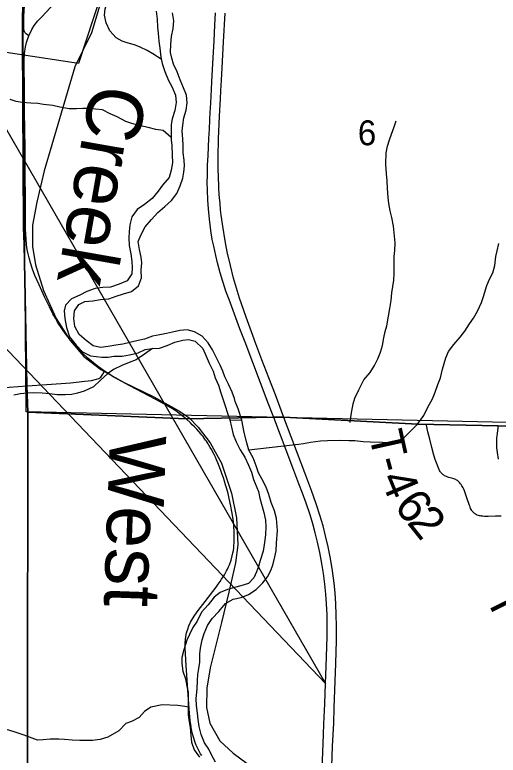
# Model space of a CAD drawing. Extents: x 0 to 34, y 0 to 22.
# Drawn here: x 4.527 to 5.34, y 17.081 to 18.326 of the extents above; entities that cross this region are included whole.
import ezdxf

# ---------------------------------------------------------------- set-up
doc = ezdxf.new("R2010")
doc.units = 0
for name, color, linetype in [('Default', 7, 'Continuous'), ('GM_X_City_Street', 7, 'Continuous'), ('GM_X_Corporation', 7, 'Continuous'), ('GM_X_Interstate_Route', 7, 'Continuous'), ('GM_X_Major_River', 7, 'Continuous'), ('GM_X_Major_River_Text', 7, 'Continuous'), ('GM_X_Minor_River', 7, 'Continuous'), ('GM_X_Rail_Line', 7, 'Continuous'), ('GM_X_Section', 7, 'Continuous'), ('GM_X_Section_Text', 7, 'Continuous'), ('GM_X_State_Route', 7, 'Continuous'), ('GM_X_Township_Road', 7, 'Continuous'), ('GM_X_Township_Road_Text', 7, 'Continuous'), ('SH_Cut_Line', 7, 'Continuous')]:
    doc.layers.add(name, color=color, linetype=linetype)

msp = doc.modelspace()

# ---------------------------------------------------------------- linework, layer by layer
at = {"layer": 'Default'}
msp.add_lwpolyline([(4.5002, 18.1545), (5.0499, 17.2016), (4.3428, 17.9419), (4.5002, 17.9419)], close=True, dxfattribs=at)
at = {"layer": 'GM_X_City_Street'}
msp.add_lwpolyline([(4.5504, 18.2908), (4.5463, 18.294), (4.5441, 18.2964), (4.543, 18.2989), (4.542, 18.303), (4.5425, 18.3233), (4.5438, 18.3504), (4.5442, 18.3738), (4.5433, 18.3874), (4.542, 18.395), (4.5399, 18.404), (4.5388, 18.408), (4.5373, 18.4113), (4.5347, 18.4151), (4.5277, 18.4229), (4.5205, 18.4317), (4.481, 18.4781), (4.4634, 18.5005), (4.4496, 18.52), (4.4317, 18.5443), (4.4197, 18.5562), (4.4037, 18.569)], dxfattribs=at)
at = {"layer": 'GM_X_Corporation'}
msp.add_lwpolyline([(4.4904, 18.7944), (4.5152, 18.7982), (4.5401, 18.7958), (4.5941, 18.7656), (4.6547, 18.7056), (4.6875, 18.6156), (4.7048, 18.5241), (4.704, 18.4796), (4.6852, 18.4001), (4.634, 18.2442), (4.4345, 18.2742), (4.3748, 18.5592), (4.5137, 18.6315)], close=True, dxfattribs=at)
at = {"layer": 'GM_X_Interstate_Route'}
for points in [[(4.9626, 17.6491), (4.9536, 17.673), (4.9145, 17.7755), (4.9056, 17.7983), (4.899, 17.8166), (4.8877, 17.8471), (4.8823, 17.8613), (4.8726, 17.892), (4.8678, 17.9088), (4.865, 17.9214), (4.8617, 17.937), (4.8593, 17.9482), (4.857, 17.9634), (4.8544, 17.9826), (4.8527, 17.9998), (4.8516, 18.0143), (4.851, 18.031), (4.8509, 18.0444), (4.8511, 18.0553), (4.8514, 18.0734), (4.8521, 18.0896), (4.8534, 18.1183), (4.8544, 18.1335), (4.8552, 18.1494), (4.8559, 18.1631), (4.8561, 18.1684), (4.8574, 18.1884), (4.8587, 18.2134), (4.8605, 18.244), (4.8625, 18.282), (4.8637, 18.3084), (4.8646, 18.3293)], [(4.9799, 17.6492), (4.9655, 17.6868), (4.9544, 17.7159), (4.9428, 17.7458), (4.9324, 17.773), (4.9275, 17.7866), (4.9161, 17.8174), (4.9052, 17.8494), (4.8951, 17.8833), (4.8897, 17.9044), (4.8846, 17.9273), (4.881, 17.9459), (4.8771, 17.9709), (4.8745, 17.9892), (4.8734, 17.9979), (4.8723, 18.0096), (4.8715, 18.0175), (4.8705, 18.0329), (4.8702, 18.042), (4.8697, 18.0489), (4.8694, 18.0709), (4.8692, 18.0914), (4.8696, 18.1134), (4.8698, 18.1179), (4.8702, 18.1301), (4.8713, 18.1554), (4.8729, 18.1848), (4.8738, 18.1984), (4.8746, 18.2162), (4.8758, 18.2369), (4.8783, 18.2808), (4.8807, 18.3289)], [(5.0438, 17.0433), (5.0455, 17.0861), (5.0465, 17.1159), (5.0471, 17.1339), (5.0485, 17.1674), (5.0499, 17.2016), (5.0509, 17.2301), (5.0525, 17.2804), (5.0527, 17.2979), (5.0524, 17.3172), (5.0516, 17.3358), (5.0504, 17.3519), (5.0487, 17.3687), (5.0463, 17.3865), (5.0435, 17.4037), (5.0401, 17.4221), (5.0364, 17.4391), (5.0326, 17.4548), (5.0283, 17.4704), (5.0238, 17.4854), (5.0173, 17.5048), (5.0111, 17.5218), (5.0051, 17.5374), (4.9949, 17.5641), (4.9626, 17.6491)], [(5.0604, 17.0619), (5.0617, 17.0961), (5.0638, 17.1352), (5.0646, 17.1606), (5.0658, 17.2059), (5.067, 17.2351), (5.0681, 17.2742), (5.0683, 17.2984), (5.068, 17.317), (5.0673, 17.3356), (5.066, 17.3542), (5.0644, 17.3703), (5.0616, 17.3912), (5.0582, 17.412), (5.0544, 17.4315), (5.05, 17.4502), (5.0456, 17.467), (5.0404, 17.4848), (5.0343, 17.5037), (5.0268, 17.5248), (5.0151, 17.5562), (4.9799, 17.6492)]]:
    msp.add_lwpolyline(points, dxfattribs=at)
at = {"layer": 'GM_X_Major_River'}
msp.add_line((4.8891, 17.6449), (4.909, 17.6445), dxfattribs=at)
for points in [[(4.7648, 18.3323), (4.7665, 18.3187), (4.7674, 18.305), (4.7683, 18.2952), (4.7696, 18.2815), (4.7709, 18.2698), (4.7726, 18.255), (4.775, 18.2444), (4.7797, 18.2308), (4.7855, 18.2157), (4.791, 18.2055), (4.7976, 18.1908), (4.7985, 18.1787), (4.7964, 18.165), (4.792, 18.1513), (4.7902, 18.1418), (4.79, 18.1285), (4.7901, 18.116), (4.791, 18.1062), (4.7919, 18.0902), (4.7921, 18.0773), (4.7903, 18.0648), (4.787, 18.0526), (4.7758, 18.0396), (4.7683, 18.0293), (4.7582, 18.0174), (4.7451, 18.007), (4.733, 17.9989), (4.724, 17.9866), (4.7204, 17.9729), (4.7194, 17.9612), (4.7187, 17.9509), (4.7196, 17.9384), (4.7221, 17.9244), (4.7241, 17.9115), (4.7246, 17.9009), (4.724, 17.8903), (4.7162, 17.8788), (4.7029, 17.8734), (4.6882, 17.8683), (4.6749, 17.8673), (4.662, 17.8657), (4.6484, 17.8606), (4.6363, 17.8548), (4.6224, 17.8485), (4.6122, 17.8378), (4.6101, 17.8283), (4.611, 17.8154), (4.6138, 17.8002), (4.6189, 17.7844), (4.6301, 17.7705), (4.6412, 17.7596), (4.6542, 17.7525), (4.6637, 17.7515), (4.6736, 17.7505), (4.6839, 17.7506), (4.6937, 17.7519), (4.7078, 17.752), (4.7203, 17.7545), (4.7347, 17.7577), (4.7464, 17.7631), (4.7585, 17.7652), (4.7706, 17.7657), (4.7835, 17.77), (4.7963, 17.7758), (4.8096, 17.779), (4.8191, 17.7799), (4.8305, 17.7774), (4.8432, 17.765), (4.849, 17.7522), (4.8541, 17.7401), (4.8607, 17.7269), (4.8642, 17.7156)], [(4.8095, 18.0514), (4.8116, 18.0616), (4.8123, 18.0719), (4.8118, 18.0817), (4.8101, 18.0942), (4.8103, 18.1071), (4.8095, 18.1177), (4.8089, 18.1306), (4.8096, 18.1405), (4.8117, 18.153), (4.8154, 18.1656), (4.8171, 18.1781), (4.8158, 18.1907), (4.8111, 18.2035), (4.8053, 18.2167), (4.8002, 18.2303), (4.7943, 18.2431), (4.7912, 18.2529), (4.7892, 18.2628), (4.7894, 18.2764), (4.7908, 18.2897), (4.7936, 18.303), (4.7946, 18.316), (4.7926, 18.3292)], [(4.8966, 17.6808), (4.893, 17.6913), (4.8868, 17.7048), (4.8805, 17.7173), (4.877, 17.7271), (4.8723, 17.7369), (4.8661, 17.7505), (4.8595, 17.7625), (4.8525, 17.7746), (4.8425, 17.7855), (4.8295, 17.7929), (4.817, 17.7966), (4.8045, 17.7953), (4.7923, 17.7925), (4.7825, 17.7901), (4.7708, 17.7877), (4.7586, 17.7856), (4.7454, 17.7806), (4.7348, 17.7785), (4.709, 17.7722), (4.6969, 17.7705), (4.684, 17.7685), (4.6715, 17.7664), (4.659, 17.7697), (4.6471, 17.7783), (4.6352, 17.7887), (4.6278, 17.8019), (4.6262, 17.8152), (4.6275, 17.8285), (4.635, 17.8388), (4.6448, 17.8439), (4.6585, 17.8451), (4.6713, 17.8476), (4.685, 17.8485), (4.6975, 17.8528), (4.71, 17.8568), (4.7232, 17.8607), (4.7349, 17.8703), (4.7404, 17.8837), (4.7399, 17.8966), (4.7405, 17.9091), (4.7396, 17.9185), (4.7368, 17.9314), (4.7348, 17.9447), (4.7396, 17.9569), (4.7462, 17.9698), (4.7571, 17.9817), (4.7676, 17.9936), (4.7793, 18.0036), (4.7905, 18.014), (4.7995, 18.0255), (4.8051, 18.0384), (4.8095, 18.0514)], [(4.8642, 17.7156), (4.8697, 17.7031), (4.8736, 17.6906), (4.8768, 17.6801), (4.8807, 17.6683), (4.8847, 17.6563), (4.8891, 17.6449)], [(4.909, 17.6445), (4.9028, 17.6633), (4.8976, 17.6761), (4.8966, 17.6808)], [(4.8891, 17.6449), (4.8946, 17.6206), (4.8993, 17.6082), (4.9062, 17.5946), (4.9143, 17.5821), (4.9201, 17.5689), (4.9251, 17.5568), (4.9287, 17.5447), (4.9372, 17.5243), (4.9392, 17.5133), (4.9419, 17.5035), (4.9459, 17.4895), (4.9486, 17.4762), (4.9495, 17.4652), (4.9489, 17.4516), (4.9474, 17.4386), (4.9449, 17.4242), (4.9401, 17.4086), (4.9372, 17.3987), (4.9338, 17.3892), (4.9294, 17.3793), (4.92, 17.3697), (4.9071, 17.3658), (4.8965, 17.3631), (4.8851, 17.3599), (4.8726, 17.3549), (4.8624, 17.3468), (4.8523, 17.3342), (4.8414, 17.3216), (4.8336, 17.3064), (4.8268, 17.2961), (4.8208, 17.2843), (4.8164, 17.2744), (4.8112, 17.2584), (4.8079, 17.2455), (4.808, 17.2352), (4.8096, 17.2227), (4.8143, 17.2095), (4.8167, 17.1974), (4.819, 17.1868), (4.8188, 17.1754), (4.8185, 17.1621), (4.819, 17.1488), (4.8206, 17.1375), (4.8222, 17.128), (4.8231, 17.1151), (4.8243, 17.103), (4.829, 17.0901), (4.8378, 17.0777)], [(4.8645, 17.0692), (4.8579, 17.0817), (4.8533, 17.0915), (4.8464, 17.102), (4.8405, 17.116), (4.8374, 17.1296), (4.8354, 17.1414), (4.8342, 17.1516), (4.8325, 17.1649), (4.8324, 17.1763), (4.8338, 17.193), (4.8344, 17.2066), (4.8351, 17.2169), (4.8365, 17.2271), (4.8383, 17.2378), (4.8386, 17.2514), (4.8396, 17.2609), (4.8422, 17.2754), (4.8459, 17.286), (4.8515, 17.299), (4.8593, 17.3108), (4.8706, 17.323), (4.8815, 17.3364), (4.8947, 17.3433), (4.908, 17.3461), (4.9201, 17.3512), (4.9329, 17.36), (4.9442, 17.3711), (4.9521, 17.381), (4.957, 17.3906), (4.9611, 17.4008), (4.9647, 17.4145), (4.9669, 17.4248), (4.9676, 17.4377), (4.9689, 17.4589), (4.9672, 17.4794), (4.9637, 17.4923), (4.9586, 17.5059), (4.9543, 17.5195), (4.9497, 17.5316), (4.9427, 17.5456), (4.9373, 17.5558), (4.9334, 17.5679), (4.9283, 17.5811), (4.9206, 17.5939), (4.9175, 17.6064), (4.9132, 17.6235), (4.909, 17.6445)]]:
    msp.add_lwpolyline(points, dxfattribs=at)
at = {"layer": 'GM_X_Minor_River'}
for points in [[(4.7733, 18.2517), (4.7592, 18.2606), (4.7496, 18.2662), (4.7382, 18.2718), (4.7287, 18.2755), (4.718, 18.2785), (4.7078, 18.2819), (4.6978, 18.2875), (4.6868, 18.2992), (4.681, 18.3124), (4.6782, 18.3257), (4.6793, 18.3359), (4.6823, 18.3454), (4.6936, 18.3546), (4.7061, 18.3569), (4.7183, 18.3589), (4.7311, 18.3628), (4.7417, 18.3674), (4.7563, 18.3764)], [(4.7901, 18.1197), (4.7767, 18.1313), (4.7642, 18.1332), (4.7512, 18.1365), (4.7387, 18.1394), (4.7239, 18.1431), (4.7136, 18.1469), (4.6991, 18.1547), (4.6877, 18.1596), (4.6747, 18.166), (4.6629, 18.1674), (4.6527, 18.1685), (4.6417, 18.1684), (4.631, 18.1679), (4.6185, 18.1682), (4.6026, 18.1708), (4.5908, 18.1734), (4.5756, 18.1755), (4.5657, 18.177), (4.5539, 18.1777), (4.5395, 18.1787), (4.5296, 18.1802), (4.5193, 18.1835)], [(5.0912, 17.6403), (5.0935, 17.6567), (5.0964, 17.6722), (5.099, 17.6817), (5.1057, 17.6954), (5.1144, 17.7125), (5.1249, 17.7247), (5.132, 17.7366), (5.1377, 17.7476), (5.1425, 17.759), (5.1455, 17.77), (5.1481, 17.7829), (5.1499, 17.7936), (5.1529, 17.8031), (5.1558, 17.8194), (5.158, 17.8323), (5.1602, 17.8456), (5.1612, 17.8585), (5.1649, 17.8798), (5.1652, 17.8908), (5.1655, 17.9025), (5.1654, 17.9196), (5.1665, 17.9298), (5.1668, 17.9427), (5.1655, 17.9594), (5.1643, 17.9704), (5.1612, 17.9852), (5.1588, 17.9962), (5.1564, 18.009), (5.1552, 18.0189), (5.154, 18.0341), (5.1535, 18.047), (5.1523, 18.0587), (5.1515, 18.075), (5.1521, 18.094), (5.1539, 18.105), (5.1573, 18.116), (5.1606, 18.1255), (5.1651, 18.1377), (5.1684, 18.1479)], [(5.2044, 17.6378), (5.2154, 17.6525), (5.2221, 17.6662), (5.23, 17.6803), (5.2345, 17.6917), (5.2386, 17.7043), (5.2431, 17.7157), (5.2468, 17.7301), (5.2523, 17.7491), (5.2568, 17.7597), (5.2658, 17.7716), (5.2764, 17.7838), (5.2843, 17.7941), (5.2922, 17.8063), (5.2986, 17.8158), (5.3057, 17.8276), (5.3125, 17.8424), (5.3158, 17.8523), (5.321, 17.8709), (5.3255, 17.8816), (5.3311, 17.8922), (5.3345, 17.9048), (5.3366, 17.9196), (5.3388, 17.9294), (5.3414, 17.9416)], [(4.7586, 17.7652), (4.745, 17.7553), (4.7314, 17.7461), (4.7197, 17.7414), (4.7072, 17.7364), (4.6932, 17.7299), (4.683, 17.7226), (4.6713, 17.7119), (4.6596, 17.7005), (4.6437, 17.6932), (4.6323, 17.6897), (4.6228, 17.6877), (4.6118, 17.6869), (4.5985, 17.6868), (4.586, 17.689), (4.5731, 17.69), (4.559, 17.6907), (4.548, 17.6899), (4.5366, 17.6887), (4.5256, 17.6863)], [(5.2044, 17.6378), (5.1828, 17.6159), (5.1746, 17.6086), (5.1621, 17.6054), (5.1457, 17.607), (5.1252, 17.6075), (5.1134, 17.608), (5.0989, 17.6097), (5.089, 17.61), (5.073, 17.6101), (5.0529, 17.6098), (5.0411, 17.6092), (5.0244, 17.6071), (5.0127, 17.6046), (5.0043, 17.6037), (4.9941, 17.6024), (4.9206, 17.5939)], [(4.5428, 17.1148), (4.5294, 17.1193), (4.5172, 17.1234), (4.5027, 17.126), (4.4887, 17.1255), (4.4781, 17.1254), (4.4682, 17.1269), (4.4571, 17.1302), (4.4469, 17.1324), (4.4355, 17.1358), (4.426, 17.1391), (4.4123, 17.1428), (4.394, 17.1507), (4.3784, 17.1589), (4.3669, 17.1645), (4.3521, 17.1701), (4.3388, 17.1746), (4.3281, 17.1779), (4.3182, 17.1805), (4.3083, 17.1854), (4.2988, 17.1921), (4.2854, 17.203), (4.2736, 17.2125), (4.2621, 17.2211)], [(4.8185, 17.1621), (4.8134, 17.1631), (4.8016, 17.1648), (4.775, 17.1659), (4.7557, 17.1618), (4.7455, 17.1548), (4.7361, 17.1448), (4.7233, 17.1378), (4.7139, 17.1346), (4.7022, 17.1223), (4.6834, 17.1114), (4.6709, 17.1074), (4.658, 17.1061), (4.6474, 17.1059), (4.6367, 17.1061), (4.6238, 17.1067), (4.6108, 17.1076), (4.6009, 17.1079), (4.5865, 17.108), (4.5747, 17.1071), (4.5652, 17.1066), (4.5428, 17.1148)]]:
    msp.add_lwpolyline(points, dxfattribs=at)
at = {"layer": 'GM_X_Rail_Line'}
msp.add_lwpolyline([(2.1, 18.7171), (2.1, 14.1), (4.5781, 14.1), (4.5658, 14.9668), (4.5509, 15.5331), (4.5478, 16.582), (4.5489, 17.6578), (4.5474, 17.7028), (4.5429, 17.9404), (4.5419, 17.9684), (4.5402, 18.2851), (4.5408, 18.3763), (4.5397, 18.3961), (4.5397, 18.4045), (4.5399, 18.4424), (4.5403, 18.5054), (4.5462, 18.6416), (3.8456, 18.6615), (3.8442, 18.6615), (2.9234, 18.6945), (2.9222, 18.6946), (2.7892, 18.6993), (2.7864, 18.6994)], close=True, dxfattribs=at)
for points in [[(4.5408, 18.3763), (4.5402, 18.2851), (4.5419, 17.9684), (4.5429, 17.9404), (4.5474, 17.7028), (4.5489, 17.6578), (4.8158, 17.6467), (4.9624, 17.6496), (4.9797, 17.6498), (5.2052, 17.638), (5.3403, 17.635), (5.6743, 17.6274), (5.6656, 16.9939), (5.6628, 16.7899), (5.6628, 16.7878), (5.6614, 16.7344), (5.6594, 16.6485), (5.9824, 16.6436), (7.149, 16.6283)], [(4.6826, 18.3838), (4.6563, 18.2957), (4.6283, 18.2384), (4.5765, 18.0637), (4.5642, 18.0108), (4.5567, 17.9726), (4.5567, 17.9364), (4.5619, 17.9054), (4.5752, 17.8626), (4.5966, 17.8153), (4.6202, 17.7784), (4.6431, 17.7518), (4.6718, 17.7296), (4.7102, 17.7082), (4.7611, 17.6839), (4.8039, 17.6595), (4.8164, 17.6514)], [(7.149, 16.6283), (5.9824, 16.6436), (5.6594, 16.6485), (5.6614, 16.7344), (5.6628, 16.7878), (5.6628, 16.7899), (5.6656, 16.9939), (5.6743, 17.6274), (5.3403, 17.635), (5.2052, 17.638), (4.9797, 17.6498), (4.9624, 17.6496), (4.8158, 17.6467), (4.5489, 17.6578), (4.5478, 16.582), (4.5509, 15.5331), (4.5658, 14.9668), (4.5781, 14.1), (8.76, 14.1)], [(4.8164, 17.6514), (4.8198, 17.6491), (4.8353, 17.6329), (4.8558, 17.6063), (4.8748, 17.5719), (4.8919, 17.5215), (4.9003, 17.4805), (4.9022, 17.435), (4.8984, 17.4048), (4.8874, 17.3553), (4.8748, 17.3044), (4.8556, 17.2283), (4.8504, 17.1936), (4.8497, 17.1611), (4.8549, 17.1353), (4.8718, 17.1053), (4.8946, 17.0844), (4.9288, 17.0592)]]:
    msp.add_lwpolyline(points, dxfattribs=at)
at = {"layer": 'GM_X_Section'}
msp.add_lwpolyline([(5.7131, 18.626), (5.685, 17.6333), (4.5464, 17.6585), (4.5407, 18.3336), (4.5473, 18.6426)], close=True, dxfattribs=at)
at = {"layer": 'GM_X_State_Route'}
for points in [[(4.5718, 18.3223), (4.5946, 18.3462)], [(4.5473, 18.2813), (4.5483, 18.2847), (4.5504, 18.2908), (4.5556, 18.3014), (4.5596, 18.3078), (4.5657, 18.316), (4.5718, 18.3223)], [(4.678, 17.7266), (4.6678, 17.7344), (4.6596, 17.7406), (4.6497, 17.7489), (4.6405, 17.7576), (4.6325, 17.7659), (4.6262, 17.7727), (4.6203, 17.7796), (4.6166, 17.7842), (4.6122, 17.7899), (4.6073, 17.7968), (4.5991, 17.8095), (4.5953, 17.816), (4.5913, 17.8231), (4.5854, 17.8348), (4.5773, 17.852), (4.5682, 17.872), (4.561, 17.8875), (4.5567, 17.8983), (4.5532, 17.9091), (4.5511, 17.9173), (4.5493, 17.9243), (4.548, 17.9317), (4.5469, 17.9392), (4.546, 17.949), (4.5455, 17.9571), (4.5453, 17.9662), (4.5452, 17.9747), (4.5448, 17.9855), (4.5448, 18.023), (4.5446, 18.0518), (4.5444, 18.0953), (4.544, 18.1383), (4.5435, 18.1586), (4.5435, 18.1689), (4.5433, 18.1908), (4.5433, 18.2113), (4.5428, 18.2311), (4.543, 18.2504), (4.5435, 18.2607), (4.545, 18.2723), (4.5468, 18.2796), (4.5473, 18.2813)], [(4.5021, 17.6986), (4.5476, 17.7023), (4.5809, 17.7045), (4.6206, 17.7073), (4.6449, 17.7098), (4.6561, 17.7112), (4.6647, 17.7133), (4.6687, 17.7146), (4.6717, 17.717), (4.675, 17.7216), (4.678, 17.7266)], [(4.816, 17.6461), (4.806, 17.6542), (4.7979, 17.6602), (4.783, 17.6693), (4.7631, 17.6799), (4.7207, 17.702), (4.6934, 17.7165), (4.678, 17.7266)], [(4.8415, 17.0806), (4.8395, 17.0837), (4.8372, 17.0878), (4.8355, 17.0914), (4.834, 17.0945), (4.8323, 17.0981), (4.8312, 17.101), (4.8299, 17.1044), (4.8287, 17.1081), (4.8277, 17.1114), (4.8266, 17.1156), (4.8256, 17.1198), (4.8245, 17.1245), (4.8238, 17.1289), (4.8223, 17.1393), (4.8211, 17.1517), (4.8194, 17.1746), (4.8153, 17.232), (4.814, 17.2514), (4.8136, 17.2619), (4.8137, 17.2693), (4.8141, 17.2755), (4.8149, 17.2809), (4.8162, 17.2869), (4.818, 17.2928), (4.8201, 17.2986), (4.8229, 17.3048), (4.8261, 17.3107), (4.8297, 17.3165), (4.8354, 17.3245), (4.8471, 17.3398), (4.8657, 17.3639), (4.869, 17.3685), (4.8723, 17.3731), (4.875, 17.377), (4.8775, 17.3808), (4.8797, 17.3842), (4.8816, 17.3879), (4.8834, 17.391), (4.8851, 17.3942), (4.8867, 17.3981), (4.888, 17.4014), (4.8908, 17.4091), (4.8929, 17.4163), (4.8941, 17.4215), (4.8949, 17.4254), (4.8954, 17.4293), (4.8958, 17.4328), (4.8963, 17.4392), (4.8963, 17.4448), (4.896, 17.4554), (4.8953, 17.4672), (4.8942, 17.4778), (4.8923, 17.491), (4.8907, 17.5), (4.8878, 17.5127), (4.8859, 17.5209), (4.8836, 17.529), (4.8817, 17.536), (4.8797, 17.5421), (4.878, 17.5478), (4.876, 17.5534), (4.8737, 17.5598), (4.8708, 17.5674), (4.8689, 17.5725), (4.8666, 17.5778), (4.8645, 17.5825), (4.8624, 17.5869), (4.8603, 17.5909), (4.8583, 17.5946), (4.8559, 17.5988), (4.8535, 17.6027), (4.8524, 17.6045), (4.8511, 17.6065), (4.8496, 17.6089), (4.848, 17.611), (4.8459, 17.6141), (4.8438, 17.6168), (4.8419, 17.6193), (4.84, 17.6215), (4.8364, 17.6257), (4.8331, 17.6293), (4.8293, 17.6333), (4.8257, 17.6368), (4.8224, 17.64), (4.816, 17.6461)]]:
    msp.add_lwpolyline(points, dxfattribs=at)
at = {"layer": 'GM_X_Township_Road'}
for points in [[(5.3453, 17.483), (5.336, 17.4828), (5.3236, 17.4824), (5.3201, 17.4824), (5.3171, 17.4825), (5.3146, 17.4828), (5.3124, 17.4831), (5.3105, 17.4834), (5.3088, 17.4839), (5.307, 17.4843), (5.3052, 17.485), (5.304, 17.4855), (5.3024, 17.4864), (5.3011, 17.4873), (5.2999, 17.4881), (5.2988, 17.4891), (5.2976, 17.4903), (5.2967, 17.4914), (5.2958, 17.4927), (5.2949, 17.4942), (5.294, 17.496), (5.2929, 17.4986), (5.2919, 17.5012), (5.2874, 17.514), (5.2834, 17.5257), (5.2824, 17.5282), (5.2812, 17.5308), (5.2803, 17.5326), (5.2794, 17.5342), (5.2782, 17.5361), (5.2771, 17.5377), (5.2754, 17.5398), (5.2741, 17.541), (5.2728, 17.542), (5.2717, 17.5429), (5.2703, 17.5438), (5.269, 17.5445), (5.2676, 17.5452), (5.2659, 17.5458), (5.264, 17.5463), (5.2574, 17.5482), (5.2554, 17.5488), (5.2535, 17.5495), (5.2518, 17.5503), (5.2502, 17.5511), (5.249, 17.5518), (5.2477, 17.5528), (5.2466, 17.5536), (5.2454, 17.5547), (5.2444, 17.5557), (5.2434, 17.557), (5.2426, 17.5581), (5.2417, 17.5596), (5.2409, 17.5613), (5.2402, 17.5629), (5.2345, 17.5785), (5.2322, 17.5855), (5.2288, 17.5986), (5.2254, 17.6124), (5.2221, 17.6248), (5.2198, 17.6361)], [(5.341, 17.579), (5.3403, 17.5828), (5.3396, 17.5864), (5.339, 17.5902), (5.3385, 17.5941), (5.3382, 17.5977), (5.338, 17.601), (5.3379, 17.6046), (5.3378, 17.608), (5.338, 17.6114), (5.3382, 17.615), (5.3385, 17.6182), (5.3401, 17.6312), (5.3405, 17.6345)]]:
    msp.add_lwpolyline(points, dxfattribs=at)
at = {"layer": 'SH_Cut_Line'}
for points in [[(2.1, 14.1), (4.5781, 14.1), (4.5658, 14.9668), (4.5509, 15.5331), (4.5478, 16.582), (4.5489, 17.6578), (4.8158, 17.6467), (4.9624, 17.6496), (4.9797, 17.6498), (5.2052, 17.638), (5.3403, 17.635), (5.6743, 17.6274), (5.6656, 16.9939), (5.6628, 16.7899), (5.6628, 16.7878), (5.6614, 16.7344), (5.6594, 16.6485), (5.9824, 16.6436), (7.149, 16.6283)], [(7.149, 16.6283), (5.9824, 16.6436), (5.6594, 16.6485), (5.6614, 16.7344), (5.6628, 16.7878), (5.6628, 16.7899), (5.6656, 16.9939), (5.6743, 17.6274), (5.3403, 17.635), (5.2052, 17.638), (4.9797, 17.6498), (4.9624, 17.6496), (4.8158, 17.6467), (4.5489, 17.6578), (4.5478, 16.582), (4.5509, 15.5331), (4.5658, 14.9668), (4.5781, 14.1), (8.9, 14.1)]]:
    msp.add_lwpolyline(points, dxfattribs=at)

# ---------------------------------------------------------------- texts
at = {"layer": 'GM_X_Major_River_Text'}
for s, rotation, p in [('Creek', 260.0005, (4.6567, 18.2127)), ('West', 268.0008, (4.6872, 17.6206))]:
    msp.add_text(s, height=0.09469, rotation=rotation, dxfattribs=at).set_placement(p)
at = {"layer": 'GM_X_Section_Text'}
msp.add_text('6', height=0.0419, rotation=0, dxfattribs=at).set_placement((5.1041, 18.1067))
at = {"layer": 'GM_X_Township_Road_Text'}
for s, rotation, p in [('T', 282.5414, (5.1224, 17.6211)), ('-', 285.1036, (5.1323, 17.577)), ('4', 292.6432, (5.141, 17.5467)), ('6', 309.0057, (5.1635, 17.4993)), ('2', 308.7801, (5.1855, 17.4721)), ('T', 296.3351, (5.3183, 17.3458))]:
    msp.add_text(s, height=0.0568, rotation=rotation, dxfattribs=at).set_placement(p)

doc.saveas('drawing.dxf')
